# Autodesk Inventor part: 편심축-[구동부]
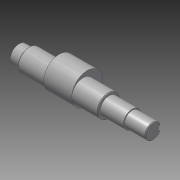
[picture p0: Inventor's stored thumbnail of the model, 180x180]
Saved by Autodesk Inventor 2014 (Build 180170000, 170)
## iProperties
Created: 2015-10
Part Number: 편심축-[구동부]
Document SubType Name: Modeling
Designer: mdu
Density: 7.86 g/cm^3
Material: 강철, 연강
Mass: 1216.6 g
Surface Area: 217.48 cm^2
Volume: 154.784 cm^3
Appearance: 강철
Author: mdu
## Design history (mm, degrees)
sketch "스케치1"
  geometry: L1 (-20.5, -41.331)-(-20.5, 32.669) reference; L2 (7.5, -30.031)-(7.5, 21.369) reference; L3 (135.5, -30.331)-(135.5, 21.669) reference; L4 (121.5, 21.369)-(121.5, -30.031) reference; L5 (184.5, -4.331)-(-7.5, -4.331); L6 (184.5, -4.331)-(184.5, 6.669); L7 (154.5, 8.169)-(121.5, 8.169); L8 (121.5, 8.169)-(121.5, 11.669); L9 (121.5, 11.669)-(7.5, 11.669); L10 (7.5, 11.669)-(7.5, 8.169); L11 (7.5, 8.169)-(-7.5, 8.169); L12 (-7.5, 8.169)-(-7.5, -4.331); L13 (154.5, 8.169)-(154.5, 6.669); L14 (154.5, 6.669)-(184.5, 6.669); C1 r 32.5 at (64.5, -4.331) reference; 1 further point
  constraints: 21 end point, 8 perpendicular, 5 point on line, 1 collinear
  dimensions: "d1" = 25 diameter of L11 L5; "d2" = 32 diameter of L9 L5; "d4" = 15 distance of L10.end L11.end; "d15" = 33 distance of L7.start L7.end; "d26" = 30 distance of L13.end L6.end; "d36" = 22 diameter of L14 L5
revolve "회전1" sketch "스케치1" stored, may be unused: angle "d6" = 90 deg
node "작업 평면1"
sketch "스케치2"
  geometry: C1 r 16 at (0, 0) reference; C2 r 22 at (0, 6)
  constraints: 1 centre point, 1 vertical alignment
  dimensions: "d34" = 6 distance of C2.centre C1.centre; "d35" = 44 diameter of C2
extrude "돌출1" join sketch "스케치2" stored distance "d9" = 40; taper "d10" = 0 deg
chamfer "모따기1" distance "d11" = 1; stored, may be unused: second distance "d12" = 2, angle "d13" = 45 deg
node "작업 평면2"
sketch "스케치3"
  geometry: L1 (-15, -10)-(-15, 10) reference; L2 (-15, 3)-(0, 3); L3 (0, -3)-(-15, -3); A1 r 3 centre (0, 0) between (0, -3) and (0, 3); 2 further points
  constraints: 4 end point, 2 perpendicular, 2 point on circle, 2 point on line, 2 tangent, 1 centre point, 1 horizontal alignment, 1 midpoint
  dimensions: "d16" = 18 dimension on A1 L1; "d17" = 6 distance between parallel lines of L3 L2
extrude "돌출2" cut sketch "스케치3" distance "d18" = 3.5; taper "d19" = 0 deg
node "솔리드1"
node "참조1"
node "참조2"
node "참조3"
node "참조4"
node "참조5"
other parameters: "d30" = 35
